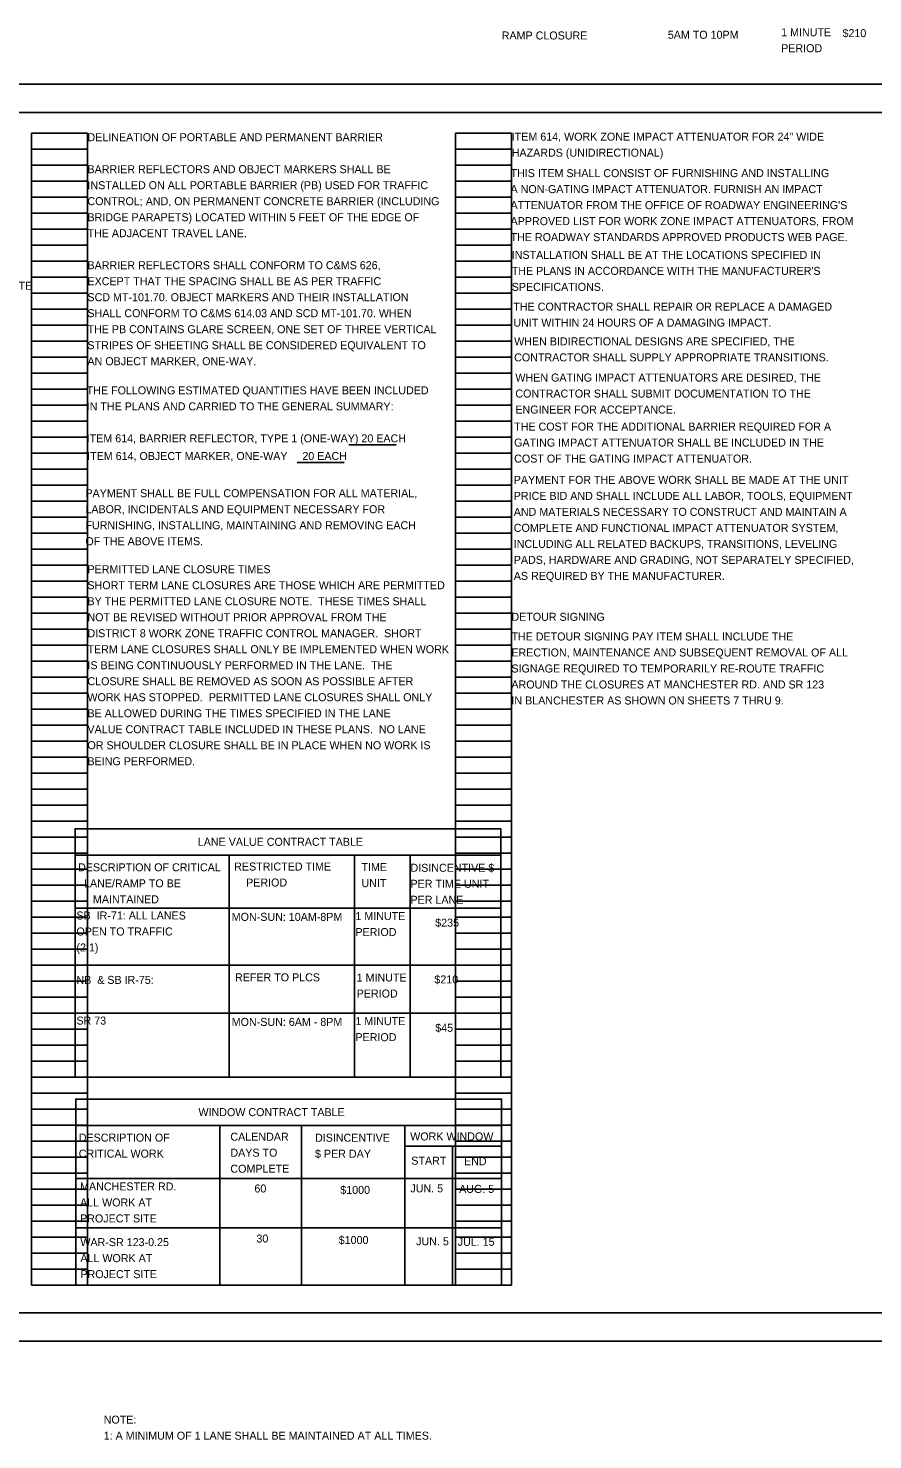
# Model space of a CAD drawing. Extents: x -98 to 46, y -2 to 66.
# Drawn here: x 8.78 to 23.56, y -1.72 to 22.98 of the extents above; entities that cross this region are included whole.
import ezdxf

# ---------------------------------------------------------------- set-up
doc = ezdxf.new("R2010")
doc.units = 0
for name, color, linetype in [('Default', 7, 'Continuous'), ('SC_Scratch1', 7, 'Continuous'), ('SH_Border', 7, 'Continuous'), ('SH_Cut_Line', 7, 'Continuous'), ('SH_Data', 7, 'Continuous')]:
    doc.layers.add(name, color=color, linetype=linetype)

msp = doc.modelspace()

# ---------------------------------------------------------------- linework, layer by layer
at = {"layer": 'Default'}
for p, q in [((12.298, 8.504), (12.298, 4.62)), ((14.49, 8.504), (14.49, 4.62)), ((15.464, 8.505), (15.464, 4.62)), ((9.603, 7.579), (17.051, 7.579)), ((9.603, 6.58), (17.051, 6.58)), ((9.603, 5.74), (17.051, 5.74)), ((9.615, 2.849), (17.063, 2.849)), ((9.615, 1.985), (17.064, 1.985))]:
    msp.add_line(p, q, dxfattribs=at)
msp.add_lwpolyline([(9.615, 3.774), (17.064, 3.774), (17.064, 4.238), (9.615, 4.238)], close=True, dxfattribs=at)
at = {"layer": 'SC_Scratch1'}
for p, q in [((14.393, 15.684), (15.219, 15.684)), ((13.486, 15.378), (14.312, 15.378)), ((9.603, 4.62), (9.603, 7.027)), ((17.051, 4.62), (17.051, 7.027)), ((12.137, 3.774), (12.137, 0.98)), ((13.566, 3.774), (13.566, 0.98)), ((15.374, 3.774), (15.374, 0.98)), ((17.064, 3.417), (15.374, 3.417)), ((16.204, 3.417), (16.204, 0.98))]:
    msp.add_line(p, q, dxfattribs=at)
for points in [[(9.603, 8.504), (17.051, 8.504), (17.051, 8.968), (9.603, 8.968)], [(9.603, 8.504), (17.051, 8.504), (17.051, 4.62), (9.603, 4.62)], [(9.619, 4.238), (17.064, 4.238), (17.064, 0.98), (9.619, 0.98)]]:
    msp.add_lwpolyline(points, close=True, dxfattribs=at)
at = {"layer": 'SH_Border'}
msp.add_lwpolyline([(1.5, 21.5), (33.5, 21.5), (33.5, 0.5), (1.5, 0.5)], close=True, dxfattribs=at)
at = {"layer": 'SH_Cut_Line'}
msp.add_lwpolyline([(0, 0), (34, 0), (34, 22), (0, 22)], close=True, dxfattribs=at)
at = {"layer": 'SH_Data'}
for p, q in [((8.84, 0.98), (8.84, 21.14)), ((8.84, 21.14), (9.82, 21.14)), ((9.82, 0.98), (9.82, 21.14)), ((16.26, 0.98), (16.26, 21.14)), ((16.26, 21.14), (17.24, 21.14)), ((17.24, 0.98), (17.24, 21.14)), ((8.84, 20.86), (9.82, 20.86)), ((16.26, 20.86), (17.24, 20.86)), ((8.84, 20.58), (9.82, 20.58)), ((16.26, 20.58), (17.24, 20.58)), ((8.84, 20.3), (9.82, 20.3)), ((16.26, 20.3), (17.24, 20.3)), ((8.84, 20.02), (9.82, 20.02)), ((16.26, 20.02), (17.24, 20.02)), ((8.84, 19.74), (9.82, 19.74)), ((16.26, 19.74), (17.24, 19.74)), ((8.84, 19.46), (9.82, 19.46)), ((16.26, 19.46), (17.24, 19.46)), ((8.84, 19.18), (9.82, 19.18)), ((16.26, 19.18), (17.24, 19.18)), ((8.84, 18.9), (9.82, 18.9)), ((16.26, 18.9), (17.24, 18.9)), ((8.84, 18.62), (9.82, 18.62)), ((16.26, 18.62), (17.24, 18.62)), ((8.84, 18.34), (9.82, 18.34)), ((16.26, 18.34), (17.24, 18.34)), ((8.84, 18.06), (9.82, 18.06)), ((16.26, 18.06), (17.24, 18.06)), ((8.84, 17.78), (9.82, 17.78)), ((16.26, 17.78), (17.24, 17.78)), ((8.84, 17.5), (9.82, 17.5)), ((16.26, 17.5), (17.24, 17.5)), ((8.84, 17.22), (9.82, 17.22)), ((16.26, 17.22), (17.24, 17.22)), ((8.84, 16.94), (9.82, 16.94)), ((16.26, 16.94), (17.24, 16.94)), ((8.84, 16.66), (9.82, 16.66)), ((16.26, 16.66), (17.24, 16.66)), ((8.84, 16.38), (9.82, 16.38)), ((16.26, 16.38), (17.24, 16.38)), ((8.84, 16.1), (9.82, 16.1)), ((16.26, 16.1), (17.24, 16.1)), ((8.84, 15.82), (9.82, 15.82)), ((16.26, 15.82), (17.24, 15.82)), ((8.84, 15.54), (9.82, 15.54)), ((16.26, 15.54), (17.24, 15.54)), ((8.84, 15.26), (9.82, 15.26)), ((16.26, 15.26), (17.24, 15.26)), ((8.84, 14.98), (9.82, 14.98)), ((16.26, 14.98), (17.24, 14.98)), ((8.84, 14.7), (9.82, 14.7)), ((16.26, 14.7), (17.24, 14.7)), ((8.84, 14.42), (9.82, 14.42)), ((16.26, 14.42), (17.24, 14.42)), ((8.84, 14.14), (9.82, 14.14)), ((16.26, 14.14), (17.24, 14.14)), ((8.84, 13.86), (9.82, 13.86)), ((16.26, 13.86), (17.24, 13.86)), ((8.84, 13.58), (9.82, 13.58)), ((16.26, 13.58), (17.24, 13.58)), ((8.84, 13.3), (9.82, 13.3)), ((16.26, 13.3), (17.24, 13.3)), ((8.84, 13.02), (9.82, 13.02)), ((16.26, 13.02), (17.24, 13.02)), ((8.84, 12.74), (9.82, 12.74)), ((16.26, 12.74), (17.24, 12.74)), ((8.84, 12.46), (9.82, 12.46)), ((16.26, 12.46), (17.24, 12.46)), ((8.84, 12.18), (9.82, 12.18)), ((16.26, 12.18), (17.24, 12.18)), ((8.84, 11.9), (9.82, 11.9)), ((16.26, 11.9), (17.24, 11.9)), ((8.84, 11.62), (9.82, 11.62)), ((16.26, 11.62), (17.24, 11.62)), ((8.84, 11.34), (9.82, 11.34)), ((16.26, 11.34), (17.24, 11.34)), ((8.84, 11.06), (9.82, 11.06)), ((16.26, 11.06), (17.24, 11.06)), ((8.84, 10.78), (9.82, 10.78)), ((16.26, 10.78), (17.24, 10.78)), ((8.84, 10.5), (9.82, 10.5)), ((16.26, 10.5), (17.24, 10.5)), ((8.84, 10.22), (9.82, 10.22)), ((16.26, 10.22), (17.24, 10.22)), ((8.84, 9.94), (9.82, 9.94)), ((16.26, 9.94), (17.24, 9.94)), ((8.84, 9.66), (9.82, 9.66)), ((16.26, 9.66), (17.24, 9.66)), ((8.84, 9.38), (9.82, 9.38)), ((16.26, 9.38), (17.24, 9.38)), ((8.84, 9.1), (9.82, 9.1)), ((16.26, 9.1), (17.24, 9.1)), ((8.84, 8.82), (9.82, 8.82)), ((16.26, 8.82), (17.24, 8.82)), ((8.84, 8.54), (9.82, 8.54)), ((16.26, 8.54), (17.24, 8.54)), ((8.84, 8.26), (9.82, 8.26)), ((16.26, 8.26), (17.24, 8.26)), ((8.84, 7.98), (9.82, 7.98)), ((16.26, 7.98), (17.24, 7.98)), ((8.84, 7.7), (9.82, 7.7)), ((16.26, 7.7), (17.24, 7.7)), ((8.84, 7.42), (9.82, 7.42)), ((16.26, 7.42), (17.24, 7.42)), ((8.84, 7.14), (9.82, 7.14)), ((16.26, 7.14), (17.24, 7.14)), ((8.84, 6.86), (9.82, 6.86)), ((16.26, 6.86), (17.24, 6.86)), ((8.84, 6.58), (9.82, 6.58)), ((16.26, 6.58), (17.24, 6.58)), ((8.84, 6.3), (9.82, 6.3)), ((16.26, 6.3), (17.24, 6.3)), ((8.84, 6.02), (9.82, 6.02)), ((16.26, 6.02), (17.24, 6.02)), ((8.84, 5.74), (9.82, 5.74)), ((16.26, 5.74), (17.24, 5.74)), ((8.84, 5.46), (9.82, 5.46)), ((16.26, 5.46), (17.24, 5.46)), ((8.84, 5.18), (9.82, 5.18)), ((16.26, 5.18), (17.24, 5.18)), ((8.84, 4.9), (9.82, 4.9)), ((16.26, 4.9), (17.24, 4.9)), ((8.84, 4.62), (9.82, 4.62)), ((16.26, 4.62), (17.24, 4.62)), ((8.84, 4.34), (9.82, 4.34)), ((16.26, 4.34), (17.24, 4.34)), ((8.84, 4.06), (9.82, 4.06)), ((16.26, 4.06), (17.24, 4.06)), ((8.84, 3.78), (9.82, 3.78)), ((16.26, 3.78), (17.24, 3.78)), ((8.84, 3.5), (9.82, 3.5)), ((16.26, 3.5), (17.24, 3.5)), ((8.84, 3.22), (9.82, 3.22)), ((16.26, 3.22), (17.24, 3.22)), ((8.84, 2.94), (9.82, 2.94)), ((16.26, 2.94), (17.24, 2.94)), ((8.84, 2.66), (9.82, 2.66)), ((16.26, 2.66), (17.24, 2.66)), ((8.84, 2.38), (9.82, 2.38)), ((16.26, 2.38), (17.24, 2.38)), ((8.84, 2.1), (9.82, 2.1)), ((16.26, 2.1), (17.24, 2.1)), ((8.84, 1.82), (9.82, 1.82)), ((16.26, 1.82), (17.24, 1.82)), ((8.84, 1.54), (9.82, 1.54)), ((16.26, 1.54), (17.24, 1.54)), ((8.84, 1.26), (9.82, 1.26)), ((16.26, 1.26), (17.24, 1.26)), ((8.84, 0.98), (9.82, 0.98)), ((16.26, 0.98), (17.24, 0.98))]:
    msp.add_line(p, q, dxfattribs=at)

# ---------------------------------------------------------------- texts
at = {"layer": 'Default'}
for s, p in [('1 MINUTE ', (21.956, 22.837)), ('$210', (23.029, 22.821)), ('RAMP CLOSURE', (17.068, 22.78)), ('5AM TO 10PM', (19.973, 22.792)), ('PERIOD', (21.956, 22.557)), ('PERMITTED LANE CLOSURE TIMES', (9.82, 13.44)), ('SHORT TERM LANE CLOSURES ARE THOSE WHICH ARE PERMITTED ', (9.82, 13.16)), ('BY THE PERMITTED LANE CLOSURE NOTE.  THESE TIMES SHALL ', (9.82, 12.88)), ('NOT BE REVISED WITHOUT PRIOR APPROVAL FROM THE ', (9.82, 12.6)), ('DISTRICT 8 WORK ZONE TRAFFIC CONTROL MANAGER.  SHORT ', (9.82, 12.32)), ('TERM LANE CLOSURES SHALL ONLY BE IMPLEMENTED WHEN WORK ', (9.82, 12.04)), ('IS BEING CONTINUOUSLY PERFORMED IN THE LANE.  THE ', (9.82, 11.76)), ('CLOSURE SHALL BE REMOVED AS SOON AS POSSIBLE AFTER ', (9.82, 11.48)), ('WORK HAS STOPPED.  PERMITTED LANE CLOSURES SHALL ONLY ', (9.82, 11.2)), ('BE ALLOWED DURING THE TIMES SPECIFIED IN THE LANE ', (9.82, 10.92)), ('VALUE CONTRACT TABLE INCLUDED IN THESE PLANS.  NO LANE ', (9.82, 10.64)), ('OR SHOULDER CLOSURE SHALL BE IN PLACE WHEN NO WORK IS ', (9.82, 10.36)), ('BEING PERFORMED.', (9.82, 10.08)), ('LANE VALUE CONTRACT TABLE', (11.75, 8.67)), ('DESCRIPTION OF CRITICAL ', (9.656, 8.224)), ('RESTRICTED TIME ', (12.387, 8.238)), ('TIME ', (14.614, 8.227)), ('DISINCENTIVE $ ', (15.471, 8.216)), ('  LANE/RAMP TO BE ', (9.656, 7.944)), ('    PERIOD', (12.387, 7.958)), ('UNIT', (14.614, 7.947)), ('PER TIME UNIT', (15.471, 7.936)), ('     MAINTAINED', (9.656, 7.664)), ('PER LANE', (15.471, 7.656)), ('SB  IR-71: ALL LANES', (9.627, 7.381)), ('MON-SUN: 10AM-8PM ', (12.344, 7.357)), ('1 MINUTE ', (14.508, 7.371)), ('OPEN TO TRAFFIC', (9.627, 7.101)), ('PERIOD', (14.508, 7.091)), ('$235', (15.904, 7.255)), ('(2:1)', (9.627, 6.821)), ('REFER TO PLCS', (12.401, 6.299)), ('1 MINUTE ', (14.53, 6.295)), ('NB  & SB IR-75:', (9.627, 6.254)), ('$210', (15.889, 6.262)), ('PERIOD', (14.53, 6.015)), ('SR 73', (9.627, 5.542)), ('MON-SUN: 6AM - 8PM', (12.344, 5.519)), ('1 MINUTE ', (14.508, 5.532)), ('$45', (15.904, 5.416)), ('PERIOD', (14.508, 5.252)), ('WINDOW CONTRACT TABLE', (11.762, 3.94)), ('DESCRIPTION OF', (9.668, 3.494)), ('CALENDAR', (12.321, 3.51)), ('DISINCENTIVE', (13.801, 3.492)), ('WORK WINDOW', (15.466, 3.515)), ('CRITICAL WORK', (9.668, 3.214)), ('DAYS TO', (12.321, 3.23)), ('$ PER DAY', (13.801, 3.212)), ('START', (15.485, 3.091)), ('END', (16.408, 3.082)), ('COMPLETE', (12.321, 2.95)), ('MANCHESTER RD.', (9.691, 2.64)), ('60', (12.741, 2.604)), ('$1000', (14.243, 2.579)), ('JUN. 5', (15.469, 2.606)), ('AUG. 5', (16.322, 2.597)), ('ALL WORK AT', (9.691, 2.36)), ('PROJECT SITE', (9.691, 2.08)), ('WAR-SR 123-0.25', (9.696, 1.665)), ('30', (12.776, 1.728)), ('$1000', (14.216, 1.702)), ('JUN. 5', (15.57, 1.68)), ('JUL. 15', (16.298, 1.671)), ('ALL WORK AT', (9.696, 1.385)), ('PROJECT SITE', (9.696, 1.105))]:
    msp.add_text(s, height=0.14, dxfattribs=at).set_placement(p)
at = {"layer": 'SC_Scratch1'}
for s, p in [('DELINEATION OF PORTABLE AND PERMANENT BARRIER', (9.82, 21)), ('ITEM 614, WORK ZONE IMPACT ATTENUATOR FOR 24" WIDE', (17.243, 21.009)), ('HAZARDS (UNIDIRECTIONAL)', (17.243, 20.729)), ('BARRIER REFLECTORS AND OBJECT MARKERS SHALL BE', (9.82, 20.44)), ('THIS ITEM SHALL CONSIST OF FURNISHING AND INSTALLING', (17.222, 20.371)), ('INSTALLED ON ALL PORTABLE BARRIER (PB) USED FOR TRAFFIC', (9.82, 20.16)), ('CONTROL; AND, ON PERMANENT CONCRETE BARRIER (INCLUDING', (9.82, 19.88)), ('A NON-GATING IMPACT ATTENUATOR. FURNISH AN IMPACT', (17.222, 20.091)), ("ATTENUATOR FROM THE OFFICE OF ROADWAY ENGINEERING'S", (17.222, 19.811)), ('BRIDGE PARAPETS) LOCATED WITHIN 5 FEET OF THE EDGE OF', (9.82, 19.6)), ('APPROVED LIST FOR WORK ZONE IMPACT ATTENUATORS, FROM', (17.222, 19.531)), ('THE ADJACENT TRAVEL LANE.', (9.82, 19.32)), ('THE ROADWAY STANDARDS APPROVED PRODUCTS WEB PAGE.', (17.222, 19.251)), ('INSTALLATION SHALL BE AT THE LOCATIONS SPECIFIED IN', (17.243, 18.941)), ('BARRIER REFLECTORS SHALL CONFORM TO C&MS 626,', (9.82, 18.76)), ("THE PLANS IN ACCORDANCE WITH THE MANUFACTURER'S", (17.243, 18.661)), ('WITH TOP-MOUNTED EMERGENCY FLASHING LIGHTS AND COMPLETE', (2.426, 18.4)), ('EXCEPT THAT THE SPACING SHALL BE AS PER TRAFFIC', (9.82, 18.48)), ('SCD MT-101.70. OBJECT MARKERS AND THEIR INSTALLATION', (9.82, 18.2)), ('SPECIFICATIONS.', (17.243, 18.381)), ('SHALL CONFORM TO C&MS 614.03 AND SCD MT-101.70. WHEN', (9.82, 17.92)), ('THE CONTRACTOR SHALL REPAIR OR REPLACE A DAMAGED', (17.271, 18.035)), ('UNIT WITHIN 24 HOURS OF A DAMAGING IMPACT.', (17.271, 17.755)), ('THE PB CONTAINS GLARE SCREEN, ONE SET OF THREE VERTICAL', (9.82, 17.64)), ('WHEN BIDIRECTIONAL DESIGNS ARE SPECIFIED, THE', (17.285, 17.427)), ('STRIPES OF SHEETING SHALL BE CONSIDERED EQUIVALENT TO', (9.82, 17.36)), ('AN OBJECT MARKER, ONE-WAY.', (9.82, 17.08)), ('CONTRACTOR SHALL SUPPLY APPROPRIATE TRANSITIONS.', (17.285, 17.147)), ('WHEN GATING IMPACT ATTENUATORS ARE DESIRED, THE', (17.306, 16.794)), ('THE FOLLOWING ESTIMATED QUANTITIES HAVE BEEN INCLUDED', (9.807, 16.57)), ('CONTRACTOR SHALL SUBMIT DOCUMENTATION TO THE', (17.306, 16.514)), ('IN THE PLANS AND CARRIED TO THE GENERAL SUMMARY:', (9.807, 16.29)), ('ENGINEER FOR ACCEPTANCE.', (17.306, 16.234)), ('THE COST FOR THE ADDITIONAL BARRIER REQUIRED FOR A', (17.285, 15.936)), ('ITEM 614, BARRIER REFLECTOR, TYPE 1 (ONE-WAY) 20 EACH', (9.807, 15.73)), ('ITEM 614, OBJECT MARKER, ONE-WAY     20 EACH', (9.814, 15.421)), ('GATING IMPACT ATTENUATOR SHALL BE INCLUDED IN THE', (17.285, 15.656)), ('COST OF THE GATING IMPACT ATTENUATOR.', (17.285, 15.376)), ('PAYMENT FOR THE ABOVE WORK SHALL BE MADE AT THE UNIT', (17.278, 15.004)), ('PAYMENT SHALL BE FULL COMPENSATION FOR ALL MATERIAL,', (9.784, 14.77)), ('PRICE BID AND SHALL INCLUDE ALL LABOR, TOOLS, EQUIPMENT', (17.278, 14.724)), ('LABOR, INCIDENTALS AND EQUIPMENT NECESSARY FOR', (9.784, 14.49)), ('AND MATERIALS NECESSARY TO CONSTRUCT AND MAINTAIN A', (17.278, 14.444)), ('FURNISHING, INSTALLING, MAINTAINING AND REMOVING EACH', (9.784, 14.21)), ('COMPLETE AND FUNCTIONAL IMPACT ATTENUATOR SYSTEM,', (17.278, 14.164)), ('OF THE ABOVE ITEMS.', (9.784, 13.93)), ('INCLUDING ALL RELATED BACKUPS, TRANSITIONS, LEVELING', (17.278, 13.884)), ('PADS, HARDWARE AND GRADING, NOT SEPARATELY SPECIFIED,', (17.278, 13.604)), ('AS REQUIRED BY THE MANUFACTURER.', (17.278, 13.324)), ('DETOUR SIGNING', (17.237, 12.607)), ('THE DETOUR SIGNING PAY ITEM SHALL INCLUDE THE ', (17.237, 12.263)), ('ERECTION, MAINTENANCE AND SUBSEQUENT REMOVAL OF ALL ', (17.237, 11.983)), ('SIGNAGE REQUIRED TO TEMPORARILY RE-ROUTE TRAFFIC ', (17.237, 11.703)), ('AROUND THE CLOSURES AT MANCHESTER RD. AND SR 123', (17.237, 11.423)), ('IN BLANCHESTER AS SHOWN ON SHEETS 7 THRU 9.', (17.237, 11.143)), ('NOTE:', (10.104, -1.441)), ('1: A MINIMUM OF 1 LANE SHALL BE MAINTAINED AT ALL TIMES.', (10.104, -1.721))]:
    msp.add_text(s, height=0.14, dxfattribs=at).set_placement(p)

doc.saveas('drawing.dxf')
